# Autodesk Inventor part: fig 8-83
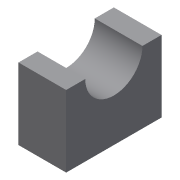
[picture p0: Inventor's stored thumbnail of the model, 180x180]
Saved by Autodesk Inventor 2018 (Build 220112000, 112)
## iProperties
Shininess: 77.0
Length Units: 11269
Angle Units: 11279
Time Units: 11290
Mass Units: 11283
Length Display Precision: 3
Angle Display Precision: 2
Created: 2002-01
Part Number: fig 8-83
Document SubType Name: Modeling
Designer: ***
Density: 1 g/cm^3
Material: Generic
Appearance: Default
Density: 0.0
Volumn: 0.0
Area: 0.0
PropertySet Name: Model Information
Control State: 0
Master: False
Checked Out: False
Author: ***
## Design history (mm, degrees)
sketch "Sketch5"
  geometry: L1 (-22.226, 10.275)-(-14.226, 10.275); L2 (9.774, 10.275)-(17.774, 10.275); L3 (17.774, 10.275)-(17.774, -19.725); L4 (17.774, -19.725)-(-22.226, -19.725); L5 (-22.226, -19.725)-(-22.226, 10.275); A1 r 12 centre (-2.226, 10.275) between (-14.226, 10.275) and (9.774, 10.275)
  constraints: 10 end point, 2 equal length, 2 parallel, 2 point on circle, 1 centre point, 1 collinear, 1 horizontal, 1 perpendicular, 1 point on line
  dimensions: "d7" = 40 distance of L3.end L4.end; "d8" = 30 distance of L2.end L3.end; "d9" = 12 radius of A1
extrude "Extrusion2" new body sketch "Sketch5" distance "d10" = 20; taper "d11" = 0 deg
workplane "Work Plane3"
sketch "Sketch6"
  geometry: L1 (19.321, -18.091)-(12.314, -18.091); L2 (12.314, -18.091)-(12.314, -11.217); L3 (12.314, -11.217)-(7.026, -11.217); L4 (7.026, -11.217)-(7.026, 7.425); L5 (7.026, 7.425)-(7.026, 14.035); L6 (7.026, 14.035)-(-10.029, 14.035)
  constraints: 12 end point, 4 parallel, 1 horizontal, 1 perpendicular
split "Split5" sketch "Sketch6"
body "Solid1"
other parameters: "d12" = 15
